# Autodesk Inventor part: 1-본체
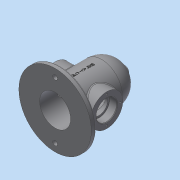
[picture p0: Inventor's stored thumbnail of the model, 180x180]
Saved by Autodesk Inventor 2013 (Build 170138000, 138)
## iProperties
Created: 2019-11
Part Number: 1-본체
Material: Generic
Document SubType Name: Modeling
Designer: Administrator
Density: 1 g/cm^3
Author: Administrator
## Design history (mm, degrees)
sketch "스케치1"
  geometry: L1 (0, 0)-(40, 0); L2 (0, 0)-(0, 130); L3 (40, 0)-(40, 90); A1 r 40 centre (0, 90) between (40, 90) and (0, 130)
  constraints: 6 end point, 2 point on circle, 1 centre point, 1 horizontal, 1 perpendicular, 1 tangent, 1 vertical
  dimensions: "d0" = 130 distance of L1.start L2.end; "d1" = 40 distance of L1.start L1.end; "d3" = 40 radius of A1
revolve "회전1" sketch "스케치1" stored, may be unused: angle "d4" = 90 deg
feature "쉘1" dims "d5" = 10
sketch "스케치2"
  geometry: C1 r 40 at (0, 0) reference; C2 r 70 at (0, 0)
  constraints: 1 centre point, 1 coincident
  dimensions: "d6" = 140 diameter of C2
extrude "돌출1" join sketch "스케치2" distance "d8" = 10; taper "d9" = 0 deg
node "작업 평면1"
sketch "스케치3"
  geometry: C1 r 7.5 at (0, 0); 1 further point
  constraints: 1 centre point, 1 coincident
  dimensions: "d11" = 15 diameter of C1
extrude "돌출2" join sketch "스케치3" stored distance "d13" = 10; taper "d14" = 0 deg
node "작업 평면2"
sketch "스케치4"
  geometry: L1 (0, -70)-(0, 70) reference; C1 r 31 at (50, 0); 1 further point
  constraints: 1 centre point, 1 horizontal alignment
  dimensions: "d16" = 62 diameter of C1; "d18" = 50 distance from line of L1 C1.centre
extrude "돌출3" join sketch "스케치4" stored distance "d19" = 10; taper "d20" = 0 deg
sketch "스케치5"
  geometry: C1 r 31 at (0, 0) reference; 2 further points
  constraints: 1 coincident
hole "구멍1" sketch "스케치5" at (0, 0) diameter "d21" = 40; stored, may be unused: countersink angle "d25" = 90 deg, drill point angle "d27" = 0 deg; dims "d22" = 6, "d23" = 4, "d24" = 2, "d26" = 15
sketch "스케치6"
  geometry: C1 r 31 at (0, 0) reference; 2 further points
  constraints: 1 coincident
hole "구멍2" sketch "스케치6" at (0, 0) diameter "d28" = 40; stored, may be unused: countersink angle "d32" = 90 deg, drill point angle "d34" = 0 deg; dims "d29" = 6, "d30" = 4, "d31" = 2, "d33" = 15
sketch "스케치7"
  geometry: C1 r 20 at (0, 0) reference; 2 further points
  constraints: 1 coincident
hole "구멍3" sketch "스케치7" at (0, 0) diameter "d35" = 33; stored, may be unused: countersink angle "d39" = 90 deg, drill point angle "d41" = 0 deg; dims "d36" = 6, "d37" = 4, "d38" = 2, "d40" = 15
sketch "스케치8"
  geometry: C1 r 20 at (0, 0) reference; 2 further points
  constraints: 1 vertical alignment
  dimensions: "d42" = 26 distance of C1.centre point (0, 26)
hole "구멍4" sketch "스케치8" at (0, 26) diameter "d43" = 3.242; stored, may be unused: countersink angle "d47" = 90 deg, drill point angle "d49" = 118 deg; dims "d44" = 8, "d45" = 4, "d46" = 2, "d48" = 10
sketch "스케치9"
  geometry: C1 r 7.5 at (0, 0) reference; 1 further point
  constraints: 1 coincident
hole "구멍5" sketch "스케치9" at (0, 0) diameter "d53" = 5.188; stored, may be unused: countersink angle "d57" = 90 deg, drill point angle "d59" = 118 deg; dims "d54" = 8, "d55" = 4, "d56" = 2, "d58" = 10
node "작업 평면4"
sketch "스케치10"
  geometry: L1 (70, 0)-(-70, 0) reference; 2 further points
  constraints: 1 vertical alignment, 1 other
  dimensions: "d61" = 50 distance from line of L1 point (0, 50)
feature "엠보싱1" sketch "스케치10" dims "d62" = 0.5, "d63" = 0
sketch "스케치11"
  geometry: C1 r 40 at (0, 0) reference; 2 further points
  constraints: 2 vertical alignment
  dimensions: "d64" = 55 distance of C1.centre point (0, 55); "d65" = 110 distance of point (0, -55) point (0, 55)
hole "구멍6" sketch "스케치11" at (0, -55), (0, 55) diameter "d66" = 9; stored, may be unused: countersink angle "d70" = 90 deg, drill point angle "d72" = 118 deg; dims "d67" = 8, "d68" = 4, "d69" = 2, "d71" = 10
fillet "모깎기1" dims "d73" = 0.3
chamfer "모따기1" distance "d74" = 1; stored, may be unused: second distance "d75" = 2, angle "d76" = 45 deg
fillet "모깎기2" dims "d77" = 3
fillet "모깎기3" dims "d78" = 3
fillet "모깎기4" dims "d79" = 3
node "솔리드1"
mirror "대칭1"
pattern_circular "원형 패턴1" dims angle "d51" = 360 deg
mirror "대칭2"
node "작업 평면3"
other parameters: "d10" = 135, "d60" = 55
